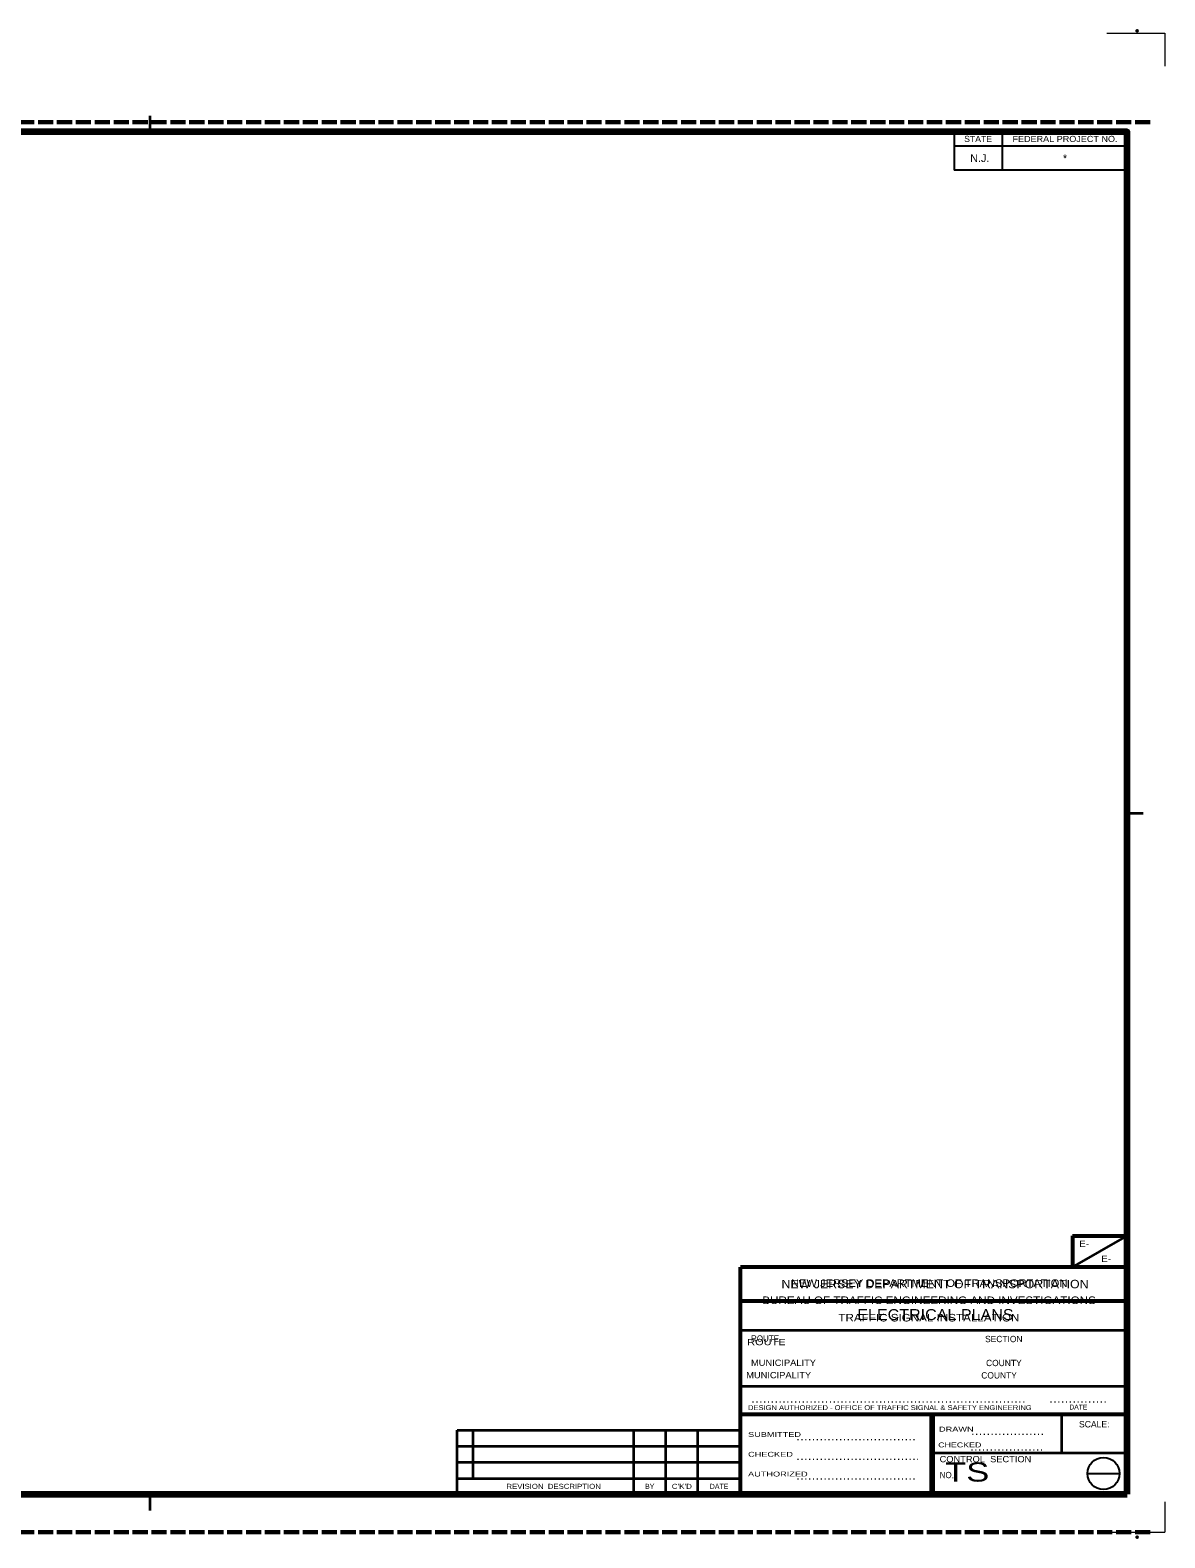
# Model space of a CAD drawing. Extents: x 214965 to 215235, y 214718 to 214897.
# Drawn here: x 215100 to 215235, y 214718.1 to 214897.4 of the extents above; entities that cross this region are included whole.
import ezdxf
from ezdxf.enums import TextEntityAlignment as Align

# ---------------------------------------------------------------- set-up
doc = ezdxf.new("R2010")
doc.units = 0
doc.header["$LTSCALE"] = 0.3
doc.header["$PDMODE"] = 32
doc.header["$PDSIZE"] = 0.15
doc.linetypes.add('DOTTED', pattern=[1.5, 0.3, -1.2])
doc.linetypes.add('LONG_DASHED', pattern=[7.5, 6, -1.5])
for name, color, linetype, lineweight in [('1', 7, 'Continuous', 35), ('25', 7, 'Continuous', 35), ('27', 7, 'Continuous', 35)]:
    doc.layers.add(name, color=color, linetype=linetype, lineweight=lineweight)

msp = doc.modelspace()

# ---------------------------------------------------------------- linework, layer by layer
at = {"layer": '1'}
for p, q in [((215114.2114, 214887.1962), (215114.2114, 214885.3062)), ((215230.4614, 214804.3062), (215232.3814, 214804.3062)), ((215114.2114, 214723.3062), (215114.2114, 214721.3862))]:
    msp.add_line(p, q, dxfattribs=at)
at = {"layer": '1', "linetype": 'LONG_DASHED', "lineweight": 60}
for p, q in [((215233.2114, 214886.4462), (214964.9874, 214886.4462)), ((215233.2114, 214718.8062), (214964.9874, 214718.8062))]:
    msp.add_line(p, q, dxfattribs=at)
at = {"layer": '1', "lineweight": 25}
for p, q in [((215209.8874, 214885.3062), (215209.8874, 214880.7342)), ((215215.6024, 214885.3062), (215215.6024, 214880.7342)), ((215230.4614, 214883.5917), (215209.8874, 214883.5917)), ((215230.4614, 214880.7342), (215209.8874, 214880.7342))]:
    msp.add_line(p, q, dxfattribs=at)
at = {"layer": '1', "lineweight": 13}
for p in [(215234.9614, 214722.4062), (215228.0614, 214718.8062)]:
    msp.add_line(p, (215234.9614, 214718.8062), dxfattribs=at)
msp.add_lwpolyline([(215228.0614, 214897.0062), (215234.9614, 214897.0062), (215234.9614, 214893.1062)], dxfattribs=at)
at = {"layer": '1', "lineweight": 158}
msp.add_lwpolyline([(215230.4614, 214723.3062), (215230.4614, 214885.3062), (214997.9614, 214885.3062), (214997.9614, 214723.3062)], close=True, dxfattribs=at)
at = {"layer": '1'}
for p in [(215231.6614, 214897.3062), (215231.6614, 214718.2062)]:
    msp.add_point(p, dxfattribs=at)
at = {"layer": '25'}
msp.add_line((215223.9614, 214750.3062), (215230.4614, 214754.0562), dxfattribs=at)
at = {"layer": '25', "lineweight": 53}
for p, q in [((215223.9614, 214754.0562), (215230.4614, 214754.0562)), ((215223.9614, 214754.0562), (215223.9614, 214750.3062)), ((215184.4614, 214723.3062), (215184.4614, 214750.3062)), ((215230.4614, 214750.3062), (215184.4614, 214750.3062)), ((215184.4614, 214746.3062), (215230.4614, 214746.3062)), ((215230.4614, 214732.7862), (215184.4614, 214732.7862)), ((215207.3614, 214732.7862), (215207.3614, 214723.3062))]:
    msp.add_line(p, q, dxfattribs=at)
at = {"layer": '25', "lineweight": 25}
msp.add_line((215225.7514, 214725.7962), (215229.5614, 214725.7962), dxfattribs=at)
msp.add_circle((215227.6622, 214725.7824), 1.9049, dxfattribs=at)
at = {"layer": '27', "lineweight": 53}
for p in [(215184.4614, 214723.3062), (215230.4614, 214750.3062)]:
    msp.add_line(p, (215184.4614, 214750.3062), dxfattribs=at)
at = {"layer": '27'}
for p, q in [((215230.4614, 214742.7762), (215184.4614, 214742.7762)), ((215230.4614, 214736.1162), (215184.4614, 214736.1162)), ((215230.4614, 214732.7862), (215184.4614, 214732.7862)), ((215207.1214, 214723.6062), (215207.1214, 214732.8462)), ((215222.6914, 214728.1962), (215222.6914, 214732.7862)), ((215150.7714, 214730.9262), (215184.4614, 214730.9262)), ((215150.7714, 214723.3062), (215150.7714, 214730.9262)), ((215152.6914, 214725.1962), (215152.6914, 214730.9262)), ((215171.7714, 214723.3062), (215171.7714, 214730.9262)), ((215175.5814, 214723.3062), (215175.5814, 214730.9262)), ((215179.3914, 214723.3062), (215179.3914, 214730.9262)), ((215150.7714, 214729.0362), (215184.4614, 214729.0362)), ((215230.4614, 214728.1962), (215207.1214, 214728.1962)), ((215150.7714, 214727.1162), (215184.4614, 214727.1162)), ((215150.7714, 214725.1962), (215184.4614, 214725.1962))]:
    msp.add_line(p, q, dxfattribs=at)
at = {"layer": '27', "linetype": 'DOTTED', "lineweight": 13}
for p, q in [((215185.9262, 214734.2964), (215218.3063, 214734.2964)), ((215221.3724, 214734.2964), (215227.9594, 214734.2964)), ((215191.2759, 214729.8384), (215205.5326, 214729.8384)), ((215191.2759, 214729.8384), (215205.5326, 214729.8384)), ((215212.0617, 214730.4715), (215220.5411, 214730.4715)), ((215191.2759, 214727.482), (215205.5781, 214727.482)), ((215191.2759, 214727.482), (215205.5781, 214727.482)), ((215211.9616, 214728.5973), (215220.4411, 214728.5973)), ((215191.2759, 214725.1347), (215205.5326, 214725.1347))]:
    msp.add_line(p, q, dxfattribs=at)

# ---------------------------------------------------------------- texts
at = {"layer": '1'}
for s, height, width, p in [('STATE', 0.7315, 1.05, (215212.7449, 214884.0832)), ('FEDERAL PROJECT NO.', 0.7315, 1.1, (215223.0809, 214884.0832)), ('N.J.', 0.9144, 1.05, (215212.9429, 214881.7057))]:
    msp.add_text(s, height=height, dxfattribs=dict(at, width=width)).set_placement(p, align=Align.CENTER)
msp.add_text('*', height=0.9144, dxfattribs=at).set_placement((215223.0809, 214881.6972), align=Align.CENTER)
at = {"layer": '25'}
for s, height, width, p in [('E-   ', 0.75, 1.15, (215225.8386, 214752.7102)), ('E-   ', 0.75, 1.15, (215228.4579, 214750.9208)), ('NEW JERSEY DEPARTMENT OF TRANSPORTATION', 1, 1.1, (215207.6189, 214747.8062)), ('ELECTRICAL PLANS', 1.3, 1.1, (215207.666, 214744.0229)), ('CONTROL  SECTION', 0.75, 1.1, (215213.6202, 214727.1162)), ('NO.', 0.75, 0.95, (215209.022, 214725.2262))]:
    msp.add_text(s, height=height, dxfattribs=dict(at, width=width)).set_placement(p, align=Align.CENTER)
for s, width, p in [('ROUTE', 0.95, (215185.7314, 214741.4562)), ('MUNICIPALITY', 1.1, (215185.7314, 214738.5762))]:
    msp.add_text(s, height=0.75, dxfattribs=dict(at, width=width)).set_placement(p)
for s, p in [('SECTION', (215213.5714, 214741.3962)), ('COUNTY', (215213.6914, 214738.5462))]:
    msp.add_text(s, height=0.75, dxfattribs=at).set_placement(p)
at = {"layer": '27'}
for s, height, width, p in [('NEW JERSEY DEPARTMENT OF TRANSPORTATION', 0.9, 1.1, (215206.9298, 214747.9662)), ('BUREAU OF TRAFFIC ENGINEERING AND INVESTIGATIONS', 0.9, 1.15, (215206.912, 214745.9262)), ('TRAFFIC SIGNAL INSTALLATION', 0.9, 1.15, (215206.8876, 214743.8562)), ('REVISION  DESCRIPTION', 0.6, 1.15, (215162.2502, 214723.9542)), ('BY', 0.6, 0.9, (215173.6792, 214723.9542)), ("C'K'D", 0.6, 1.2, (215177.5032, 214723.9542))]:
    msp.add_text(s, height=height, dxfattribs=dict(at, width=width)).set_placement(p, align=Align.CENTER)
for s, height, width, p in [('ROUTE                                                         ', 0.75, 1.3, (215185.2814, 214741.0362)), ('MUNICIPALITY', 0.75, 1.1, (215185.1614, 214737.1062)), ('DESIGN AUTHORIZED - OFFICE OF TRAFFIC SIGNAL & SAFETY ENGINEERING', 0.5823, 1.15, (215185.3803, 214733.3229)), ('DRAWN                     ', 0.5822, 1.4, (215208.0949, 214730.7627)), ('SUBMITTED                        ', 0.5823, 1.4, (215185.3803, 214730.1295)), ('CHECKED                  ', 0.5822, 1.35, (215207.9949, 214728.8885)), ('CHECKED                          ', 0.5823, 1.4, (215185.3803, 214727.7731)), ('AUTHORIZED                       ', 0.5823, 1.4, (215185.3803, 214725.4258)), ('TS     ', 2.275, 1.35, (215208.8228, 214724.8208))]:
    msp.add_text(s, height=height, dxfattribs=dict(at, width=width)).set_placement(p)
msp.add_text('COUNTY', height=0.75, dxfattribs=at).set_placement((215213.1214, 214737.0762))
for s, height, p in [('DATE', 0.5823, (215224.6694, 214733.3866)), ('SCALE:', 0.7642, (215226.563, 214731.2577)), ('DATE', 0.6, (215181.9347, 214723.9542))]:
    msp.add_text(s, height=height, dxfattribs=at).set_placement(p, align=Align.CENTER)

doc.saveas('drawing.dxf')
